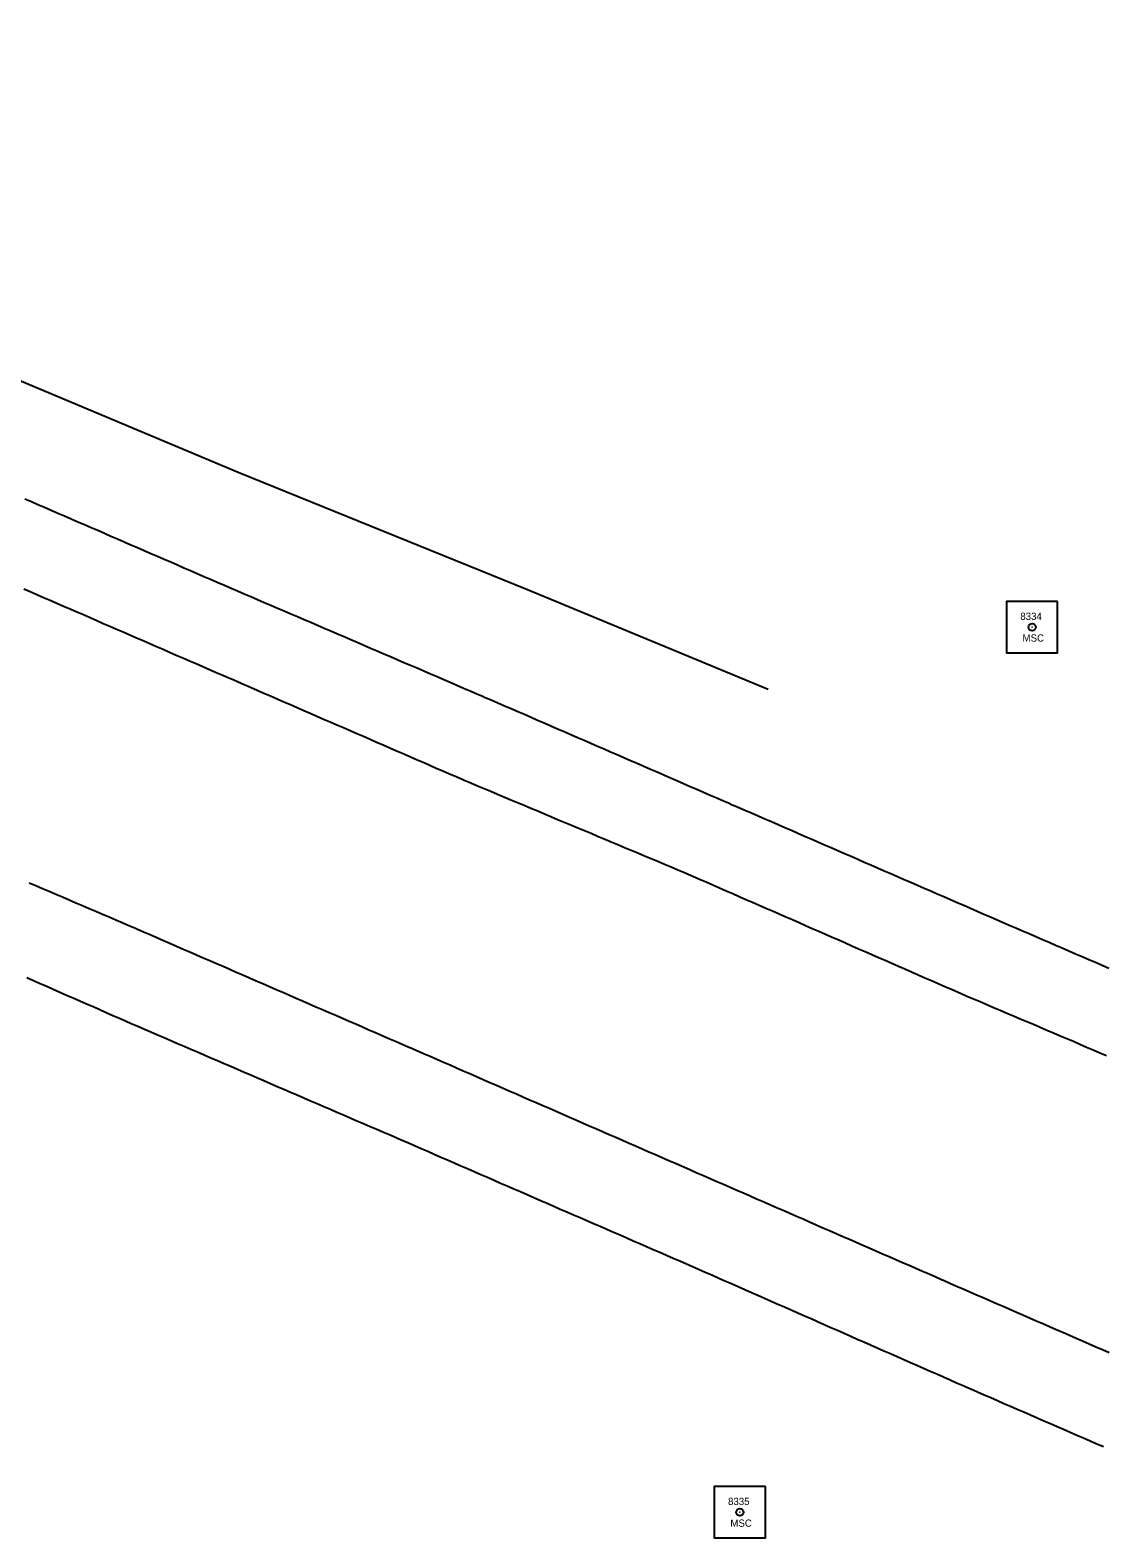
# Model space of a CAD drawing. Extents: x 205929 to 2357175, y -1785700 to 846739.
# Drawn here: x 2021028.7 to 2021177, y 813420.3 to 813628.6 of the extents above; entities that cross this region are included whole.
import ezdxf

# ---------------------------------------------------------------- set-up
doc = ezdxf.new("R2010")
doc.units = 0
for name, color, linetype in [('RD_HC_Survey', 7, 'Continuous'), ('RD_HC_txCode', 7, 'Continuous'), ('RD_Sketch1', 7, 'Continuous'), ('RD_SMD_Locator', 7, 'Continuous')]:
    doc.layers.add(name, color=color, linetype=linetype)

msp = doc.modelspace()

# ---------------------------------------------------------------- linework, layer by layer
at = {"layer": 'RD_HC_Survey'}
for points in [[(2021170.76, 813549.68), (2021163.69, 813549.68), (2021163.69, 813542.61), (2021170.76, 813542.61)], [(2021130.37, 813427.39), (2021123.3, 813427.39), (2021123.3, 813420.32), (2021130.37, 813420.32)]]:
    msp.add_lwpolyline(points, close=True, dxfattribs=at)
for centre in [(2021167.23, 813546.14), (2021126.83, 813423.85)]:
    msp.add_circle(centre, 0.5, dxfattribs=at)
at = {"layer": 'RD_Sketch1'}
for points in [[(2020911.76, 813628.62), (2020919.03, 813625.47), (2020946.75, 813613.35), (2020982.96, 813598.64), (2021020.59, 813583.02), (2021057.48, 813567.56), (2021097.46, 813551.35), (2021130.76, 813537.59)], [(2021177.83, 813499), (2021176.91, 813499.4), (2021175.99, 813499.79), (2021175.07, 813500.19), (2021174.16, 813500.59), (2021173.24, 813500.98), (2021172.32, 813501.38), (2021171.4, 813501.77), (2021170.48, 813502.17), (2021169.57, 813502.57), (2021168.65, 813502.96), (2021167.73, 813503.36), (2021166.81, 813503.75), (2021165.89, 813504.15), (2021164.97, 813504.55), (2021164.06, 813504.94), (2021163.14, 813505.34), (2021162.38, 813505.67), (2021161.46, 813506.07), (2021160.54, 813506.46), (2021159.62, 813506.86), (2021158.71, 813507.26), (2021157.79, 813507.66), (2021156.87, 813508.06), (2021155.96, 813508.46), (2021155.04, 813508.86), (2021154.12, 813509.26), (2021153.21, 813509.65), (2021152.29, 813510.05), (2021151.37, 813510.45), (2021150.46, 813510.85), (2021149.54, 813511.25), (2021148.62, 813511.65), (2021147.71, 813512.05), (2021146.79, 813512.44), (2021145.87, 813512.84), (2021144.96, 813513.24), (2021144.04, 813513.64), (2021143.12, 813514.04), (2021142.2, 813514.44), (2021141.29, 813514.84), (2021140.37, 813515.24), (2021139.45, 813515.63), (2021138.54, 813516.03), (2021137.62, 813516.43), (2021136.7, 813516.83), (2021135.79, 813517.23), (2021134.87, 813517.63), (2021133.95, 813518.03), (2021133.04, 813518.42), (2021132.12, 813518.82), (2021131.2, 813519.22), (2021130.29, 813519.62), (2021129.37, 813520.02), (2021128.45, 813520.42), (2021127.53, 813520.82), (2021126.62, 813521.22), (2021125.7, 813521.61), (2021125.48, 813521.71), (2021124.56, 813522.11), (2021123.65, 813522.51), (2021122.73, 813522.9), (2021121.81, 813523.3), (2021120.9, 813523.7), (2021119.98, 813524.1), (2021119.06, 813524.5), (2021118.14, 813524.89), (2021117.23, 813525.29), (2021116.31, 813525.69), (2021115.39, 813526.09), (2021114.48, 813526.49), (2021113.56, 813526.88), (2021112.64, 813527.28), (2021111.72, 813527.68), (2021110.81, 813528.08), (2021109.89, 813528.48), (2021108.97, 813528.87), (2021108.06, 813529.27), (2021107.14, 813529.67), (2021106.22, 813530.07), (2021105.3, 813530.47), (2021104.39, 813530.86), (2021103.47, 813531.26), (2021102.55, 813531.66), (2021101.64, 813532.06), (2021100.72, 813532.46), (2021099.8, 813532.86), (2021098.88, 813533.25), (2021097.97, 813533.65), (2021097.05, 813534.05), (2021096.13, 813534.45), (2021095.22, 813534.85), (2021094.3, 813535.24), (2021093.38, 813535.64), (2021092.46, 813536.04), (2021091.55, 813536.44), (2021091.41, 813536.5), (2021090.49, 813536.89), (2021089.57, 813537.29), (2021088.65, 813537.68), (2021087.73, 813538.08), (2021086.81, 813538.47), (2021085.9, 813538.87), (2021084.98, 813539.26), (2021084.06, 813539.66), (2021083.14, 813540.05), (2021082.22, 813540.45), (2021081.3, 813540.84), (2021080.38, 813541.23), (2021079.47, 813541.63), (2021078.55, 813542.02), (2021077.63, 813542.42), (2021076.71, 813542.81), (2021075.79, 813543.21), (2021074.87, 813543.6), (2021073.95, 813544), (2021073.04, 813544.39), (2021072.12, 813544.79), (2021071.2, 813545.18), (2021070.28, 813545.58), (2021069.36, 813545.97), (2021068.44, 813546.37), (2021067.52, 813546.76), (2021066.6, 813547.15), (2021065.69, 813547.55), (2021064.77, 813547.94), (2021063.85, 813548.34), (2021062.93, 813548.73), (2021062.01, 813549.13), (2021061.09, 813549.52), (2021060.17, 813549.92), (2021059.26, 813550.31), (2021058.34, 813550.71), (2021057.42, 813551.1), (2021056.5, 813551.5), (2021055.58, 813551.89), (2021054.59, 813552.32), (2021053.67, 813552.71), (2021052.76, 813553.11), (2021051.84, 813553.51), (2021050.92, 813553.91), (2021050, 813554.3), (2021049.09, 813554.7), (2021048.17, 813555.1), (2021047.25, 813555.5), (2021046.33, 813555.89), (2021045.42, 813556.29), (2021044.5, 813556.69), (2021043.58, 813557.09), (2021042.67, 813557.48), (2021041.75, 813557.88), (2021040.83, 813558.28), (2021039.91, 813558.68), (2021039, 813559.07), (2021038.08, 813559.47), (2021037.16, 813559.87), (2021036.24, 813560.27), (2021035.33, 813560.66), (2021034.41, 813561.06), (2021033.49, 813561.46), (2021032.57, 813561.86), (2021031.66, 813562.25), (2021030.74, 813562.65), (2021029.82, 813563.05), (2021028.9, 813563.45), (2021027.99, 813563.84)], [(2021177.53, 813486.91), (2021176.61, 813487.3), (2021175.69, 813487.69), (2021174.77, 813488.08), (2021173.85, 813488.48), (2021172.93, 813488.87), (2021172.01, 813489.26), (2021171.09, 813489.65), (2021170.17, 813490.04), (2021169.25, 813490.43), (2021168.33, 813490.82), (2021167.41, 813491.22), (2021166.49, 813491.61), (2021165.57, 813492), (2021164.65, 813492.39), (2021163.73, 813492.78), (2021162.81, 813493.17), (2021161.89, 813493.56), (2021160.97, 813493.96), (2021160.05, 813494.35), (2021159.13, 813494.74), (2021158.21, 813495.13), (2021157.91, 813495.26), (2021156.99, 813495.66), (2021156.07, 813496.06), (2021155.16, 813496.46), (2021154.24, 813496.86), (2021153.33, 813497.26), (2021152.41, 813497.66), (2021151.49, 813498.06), (2021150.58, 813498.46), (2021149.66, 813498.87), (2021148.75, 813499.27), (2021147.83, 813499.67), (2021146.91, 813500.07), (2021146, 813500.47), (2021145.08, 813500.87), (2021144.17, 813501.27), (2021143.25, 813501.67), (2021142.33, 813502.07), (2021141.42, 813502.47), (2021140.5, 813502.87), (2021139.59, 813503.27), (2021138.67, 813503.67), (2021137.75, 813504.07), (2021136.84, 813504.48), (2021135.92, 813504.88), (2021135.01, 813505.28), (2021134.09, 813505.68), (2021133.17, 813506.08), (2021132.26, 813506.48), (2021131.34, 813506.88), (2021130.43, 813507.28), (2021129.51, 813507.68), (2021128.59, 813508.08), (2021127.68, 813508.48), (2021126.76, 813508.88), (2021125.85, 813509.28), (2021124.93, 813509.68), (2021124.01, 813510.09), (2021123.1, 813510.49), (2021122.18, 813510.89), (2021121.27, 813511.29), (2021120.35, 813511.69), (2021120.09, 813511.8), (2021119.17, 813512.19), (2021118.24, 813512.58), (2021117.32, 813512.96), (2021116.4, 813513.35), (2021115.48, 813513.74), (2021114.56, 813514.12), (2021113.64, 813514.51), (2021112.71, 813514.9), (2021111.79, 813515.29), (2021110.87, 813515.67), (2021109.95, 813516.06), (2021109.03, 813516.45), (2021108.1, 813516.83), (2021107.18, 813517.22), (2021106.26, 813517.61), (2021105.34, 813517.99), (2021104.42, 813518.38), (2021103.49, 813518.77), (2021102.57, 813519.16), (2021101.65, 813519.54), (2021100.73, 813519.93), (2021099.81, 813520.32), (2021098.89, 813520.7), (2021097.96, 813521.09), (2021097.04, 813521.48), (2021095.2, 813522.25), (2021093.35, 813523.03), (2021092.43, 813523.41), (2021091.51, 813523.8), (2021090.59, 813524.19), (2021089.67, 813524.57), (2021088.74, 813524.96), (2021088.55, 813525.04), (2021087.63, 813525.44), (2021086.72, 813525.84), (2021085.8, 813526.24), (2021084.88, 813526.63), (2021083.97, 813527.03), (2021083.05, 813527.43), (2021082.13, 813527.83), (2021081.22, 813528.23), (2021080.3, 813528.63), (2021079.38, 813529.02), (2021078.47, 813529.42), (2021077.55, 813529.82), (2021076.63, 813530.22), (2021075.72, 813530.62), (2021074.8, 813531.01), (2021073.88, 813531.41), (2021072.97, 813531.81), (2021072.05, 813532.21), (2021071.13, 813532.61), (2021070.21, 813533.01), (2021069.3, 813533.4), (2021068.38, 813533.8), (2021067.46, 813534.2), (2021066.55, 813534.6), (2021065.63, 813535), (2021064.71, 813535.39), (2021063.8, 813535.79), (2021062.88, 813536.19), (2021061.96, 813536.59), (2021061.05, 813536.99), (2021060.13, 813537.39), (2021059.21, 813537.78), (2021058.3, 813538.18), (2021057.38, 813538.58), (2021056.46, 813538.98), (2021056.28, 813539.06), (2021055.36, 813539.46), (2021054.44, 813539.85), (2021053.53, 813540.25), (2021052.61, 813540.65), (2021051.69, 813541.05), (2021050.77, 813541.45), (2021049.86, 813541.85), (2021048.94, 813542.24), (2021048.02, 813542.64), (2021047.11, 813543.04), (2021046.19, 813543.44), (2021045.27, 813543.84), (2021044.35, 813544.23), (2021043.44, 813544.63), (2021042.52, 813545.03), (2021041.6, 813545.43), (2021040.69, 813545.83), (2021039.77, 813546.23), (2021038.85, 813546.62), (2021037.94, 813547.02), (2021037.02, 813547.42), (2021036.1, 813547.82), (2021035.18, 813548.22), (2021034.27, 813548.61), (2021033.35, 813549.01), (2021032.43, 813549.41), (2021031.52, 813549.81), (2021030.6, 813550.21), (2021029.68, 813550.6), (2021028.76, 813551), (2021027.85, 813551.4)], [(2021028.61, 813510.83), (2021029.53, 813510.44), (2021030.45, 813510.04), (2021031.37, 813509.65), (2021032.29, 813509.26), (2021033.2, 813508.86), (2021034.12, 813508.47), (2021035.04, 813508.07), (2021035.96, 813507.68), (2021036.88, 813507.29), (2021037.8, 813506.89), (2021038.72, 813506.5), (2021039.64, 813506.1), (2021040.56, 813505.71), (2021041.47, 813505.32), (2021042.39, 813504.92), (2021043.31, 813504.53), (2021043.48, 813504.46), (2021044.4, 813504.06), (2021045.31, 813503.66), (2021046.23, 813503.26), (2021047.15, 813502.86), (2021048.06, 813502.47), (2021048.98, 813502.07), (2021049.9, 813501.67), (2021050.81, 813501.27), (2021051.73, 813500.87), (2021052.65, 813500.47), (2021053.57, 813500.08), (2021054.48, 813499.68), (2021055.4, 813499.28), (2021056.32, 813498.88), (2021057.23, 813498.48), (2021058.15, 813498.09), (2021059.07, 813497.69), (2021059.98, 813497.29), (2021060.9, 813496.89), (2021061.82, 813496.49), (2021062.74, 813496.09), (2021063.65, 813495.7), (2021064.57, 813495.3), (2021065.49, 813494.9), (2021066.4, 813494.5), (2021067.32, 813494.1), (2021068.24, 813493.7), (2021069.15, 813493.31), (2021070.07, 813492.91), (2021070.99, 813492.51), (2021071.91, 813492.11), (2021072.82, 813491.71), (2021073.74, 813491.32), (2021074.66, 813490.92), (2021075.57, 813490.52), (2021076.49, 813490.12), (2021077.41, 813489.72), (2021078.32, 813489.32), (2021079.24, 813488.93), (2021080.16, 813488.53), (2021081.08, 813488.13), (2021081.27, 813488.05), (2021082.19, 813487.65), (2021083.1, 813487.25), (2021084.02, 813486.85), (2021084.94, 813486.45), (2021085.85, 813486.05), (2021086.77, 813485.65), (2021087.69, 813485.25), (2021088.6, 813484.85), (2021089.52, 813484.45), (2021090.44, 813484.05), (2021091.35, 813483.65), (2021092.27, 813483.25), (2021093.19, 813482.85), (2021094.1, 813482.45), (2021095.02, 813482.05), (2021095.94, 813481.65), (2021096.85, 813481.25), (2021097.77, 813480.85), (2021098.68, 813480.45), (2021099.6, 813480.06), (2021100.52, 813479.66), (2021101.43, 813479.26), (2021102.35, 813478.86), (2021103.27, 813478.46), (2021104.18, 813478.06), (2021105.1, 813477.66), (2021106.02, 813477.26), (2021106.93, 813476.86), (2021107.85, 813476.46), (2021108.77, 813476.06), (2021109.68, 813475.66), (2021110.6, 813475.26), (2021111.52, 813474.86), (2021112.43, 813474.46), (2021113.35, 813474.06), (2021114.27, 813473.66), (2021115.18, 813473.26), (2021116.1, 813472.86), (2021117.02, 813472.46), (2021117.93, 813472.07), (2021118.85, 813471.67), (2021119.07, 813471.57), (2021119.99, 813471.17), (2021120.91, 813470.77), (2021121.82, 813470.37), (2021122.74, 813469.97), (2021123.66, 813469.57), (2021124.57, 813469.17), (2021125.49, 813468.77), (2021126.4, 813468.37), (2021127.32, 813467.97), (2021128.24, 813467.57), (2021129.15, 813467.17), (2021130.07, 813466.77), (2021130.99, 813466.37), (2021131.9, 813465.97), (2021132.82, 813465.57), (2021133.74, 813465.17), (2021134.65, 813464.77), (2021135.57, 813464.37), (2021136.48, 813463.97), (2021137.4, 813463.57), (2021138.32, 813463.17), (2021139.23, 813462.77), (2021140.15, 813462.37), (2021141.07, 813461.97), (2021141.98, 813461.57), (2021142.9, 813461.17), (2021143.82, 813460.77), (2021144.73, 813460.37), (2021145.65, 813459.97), (2021146.56, 813459.57), (2021147.48, 813459.17), (2021148.4, 813458.77), (2021149.31, 813458.37), (2021150.23, 813457.98), (2021151.15, 813457.58), (2021152.06, 813457.18), (2021152.98, 813456.78), (2021153.9, 813456.38), (2021154.81, 813455.98), (2021154.97, 813455.91), (2021155.88, 813455.51), (2021156.8, 813455.11), (2021157.72, 813454.71), (2021158.63, 813454.31), (2021159.55, 813453.91), (2021160.47, 813453.51), (2021161.38, 813453.11), (2021162.3, 813452.71), (2021163.22, 813452.31), (2021164.13, 813451.91), (2021165.05, 813451.52), (2021165.97, 813451.12), (2021166.88, 813450.72), (2021167.8, 813450.32), (2021168.71, 813449.92), (2021169.63, 813449.52), (2021170.55, 813449.12), (2021171.46, 813448.72), (2021172.38, 813448.32), (2021173.3, 813447.92), (2021174.21, 813447.52), (2021175.13, 813447.12), (2021176.05, 813446.72), (2021176.96, 813446.32), (2021177.88, 813445.92)], [(2021177.09, 813432.87), (2021176.18, 813433.27), (2021175.26, 813433.67), (2021174.34, 813434.07), (2021173.43, 813434.47), (2021172.51, 813434.87), (2021171.59, 813435.27), (2021170.68, 813435.66), (2021169.76, 813436.06), (2021168.84, 813436.46), (2021167.93, 813436.86), (2021167.01, 813437.26), (2021166.09, 813437.66), (2021165.18, 813438.06), (2021164.26, 813438.45), (2021163.34, 813438.85), (2021162.43, 813439.25), (2021161.51, 813439.65), (2021160.59, 813440.05), (2021159.67, 813440.45), (2021158.76, 813440.85), (2021158.63, 813440.9), (2021157.72, 813441.3), (2021156.8, 813441.71), (2021155.89, 813442.11), (2021154.97, 813442.51), (2021154.06, 813442.91), (2021153.14, 813443.32), (2021152.23, 813443.72), (2021151.31, 813444.12), (2021150.4, 813444.52), (2021149.48, 813444.93), (2021148.56, 813445.33), (2021147.65, 813445.73), (2021146.73, 813446.13), (2021145.82, 813446.53), (2021144.9, 813446.94), (2021143.99, 813447.34), (2021143.07, 813447.74), (2021142.16, 813448.14), (2021141.24, 813448.55), (2021140.33, 813448.95), (2021139.41, 813449.35), (2021138.5, 813449.75), (2021137.58, 813450.16), (2021136.67, 813450.56), (2021135.75, 813450.96), (2021134.84, 813451.36), (2021133.92, 813451.77), (2021133.01, 813452.17), (2021132.09, 813452.57), (2021131.17, 813452.97), (2021130.26, 813453.38), (2021129.34, 813453.78), (2021128.43, 813454.18), (2021127.51, 813454.58), (2021126.6, 813454.99), (2021125.68, 813455.39), (2021124.77, 813455.79), (2021123.85, 813456.19), (2021122.94, 813456.59), (2021122.02, 813457), (2021121.11, 813457.4), (2021120.19, 813457.8), (2021119.44, 813458.13), (2021118.53, 813458.53), (2021117.61, 813458.93), (2021116.69, 813459.33), (2021115.78, 813459.72), (2021114.86, 813460.12), (2021113.94, 813460.52), (2021113.03, 813460.92), (2021112.11, 813461.32), (2021111.19, 813461.72), (2021110.28, 813462.12), (2021109.36, 813462.52), (2021108.44, 813462.91), (2021107.53, 813463.31), (2021106.61, 813463.71), (2021105.69, 813464.11), (2021104.77, 813464.51), (2021103.86, 813464.91), (2021102.94, 813465.31), (2021102.02, 813465.7), (2021101.11, 813466.1), (2021100.19, 813466.5), (2021099.27, 813466.9), (2021098.36, 813467.3), (2021097.44, 813467.7), (2021096.52, 813468.1), (2021095.61, 813468.5), (2021094.69, 813468.89), (2021093.77, 813469.29), (2021092.86, 813469.69), (2021091.94, 813470.09), (2021091.02, 813470.49), (2021090.11, 813470.89), (2021089.19, 813471.29), (2021088.27, 813471.68), (2021087.35, 813472.08), (2021086.44, 813472.48), (2021085.52, 813472.88), (2021084.6, 813473.28), (2021083.69, 813473.68), (2021082.77, 813474.08), (2021081.85, 813474.48), (2021080.94, 813474.87), (2021080.34, 813475.14), (2021079.42, 813475.53), (2021078.5, 813475.93), (2021077.58, 813476.32), (2021076.66, 813476.72), (2021075.74, 813477.11), (2021074.83, 813477.51), (2021073.91, 813477.9), (2021072.99, 813478.3), (2021072.07, 813478.7), (2021071.15, 813479.09), (2021070.24, 813479.49), (2021069.32, 813479.88), (2021068.4, 813480.28), (2021067.48, 813480.67), (2021066.56, 813481.07), (2021065.64, 813481.46), (2021064.73, 813481.86), (2021063.81, 813482.26), (2021062.89, 813482.65), (2021061.97, 813483.05), (2021061.05, 813483.44), (2021060.14, 813483.84), (2021059.22, 813484.23), (2021058.3, 813484.63), (2021057.38, 813485.02), (2021056.46, 813485.42), (2021055.54, 813485.82), (2021054.63, 813486.21), (2021053.71, 813486.61), (2021052.79, 813487), (2021051.87, 813487.4), (2021050.95, 813487.79), (2021050.04, 813488.19), (2021049.12, 813488.58), (2021048.2, 813488.98), (2021047.28, 813489.38), (2021046.36, 813489.77), (2021045.44, 813490.17), (2021044.53, 813490.56), (2021043.61, 813490.96), (2021042.69, 813491.35), (2021042.01, 813491.65), (2021041.1, 813492.05), (2021040.18, 813492.45), (2021039.26, 813492.85), (2021038.35, 813493.26), (2021037.43, 813493.66), (2021036.52, 813494.06), (2021035.6, 813494.46), (2021034.69, 813494.87), (2021033.77, 813495.27), (2021032.86, 813495.67), (2021031.94, 813496.07), (2021031.03, 813496.48), (2021030.11, 813496.88), (2021029.2, 813497.28), (2021028.28, 813497.68)]]:
    msp.add_lwpolyline(points, dxfattribs=at)
at = {"layer": 'RD_SMD_Locator'}
for centre in [(2021167.23, 813546.14), (2021126.83, 813423.85)]:
    msp.add_circle(centre, 0.001, dxfattribs=at)

# ---------------------------------------------------------------- texts
at = {"layer": 'RD_HC_txCode'}
for s, p in [('8334', (2021165.6, 813547.14)), ('MSC', (2021165.91, 813544.14)), ('8335', (2021125.2, 813424.85)), ('MSC', (2021125.52, 813421.85))]:
    msp.add_text(s, height=1, dxfattribs=at).set_placement(p)

doc.saveas('drawing.dxf')
